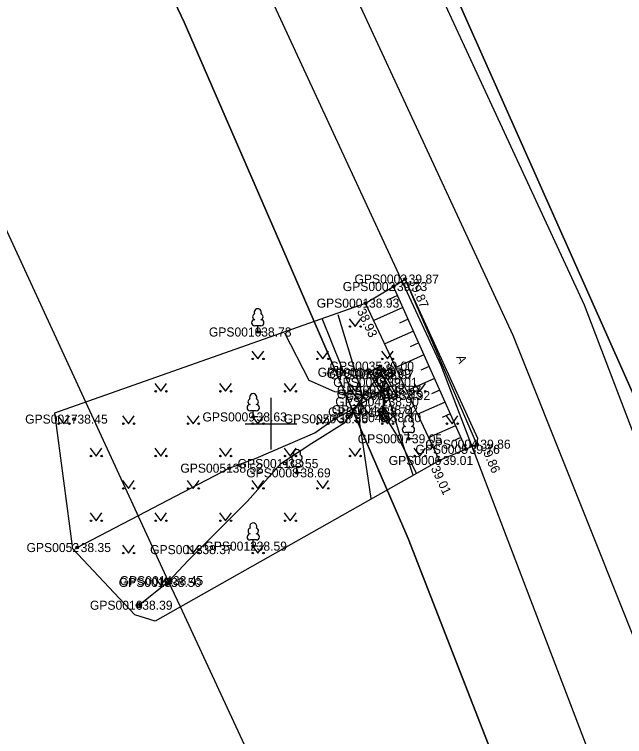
# Model space of a CAD drawing. Extents: x 626224 to 628280, y 6467750 to 6471135.
# Drawn here: x 627830.2 to 627877.3, y 6468325.8 to 6468381.6 of the extents above; entities that cross this region are included whole.
import ezdxf

# ---------------------------------------------------------------- set-up
doc = ezdxf.new("R2010")
doc.units = 0
for name, color, linetype in [('ELRAJATISMP', 7, 'Continuous'), ('HALJASTUS', 7, 'Continuous'), ('KORGUS-EH2000', 7, 'Continuous'), ('MOOTKORG-EH2000', 7, 'Continuous'), ('MOOTMPUNKT', 7, 'Continuous'), ('MOOTNR', 7, 'Continuous'), ('MOOTPIIR', 7, 'Continuous'), ('MPKAABEL', 7, 'Continuous'), ('MPOHULIIN', 7, 'Continuous'), ('PIIR', 7, 'Continuous'), ('POST', 7, 'Continuous'), ('PUU', 7, 'Continuous'), ('RAJATIS', 7, 'Continuous'), ('RELJEEF', 7, 'Continuous'), ('SIRAJATIS', 7, 'Continuous'), ('SITRASS', 7, 'Continuous'), ('TEE', 7, 'Continuous'), ('Tee Liiklusala', 7, 'Continuous'), ('Tee Põhimaantee Püsikate', 7, 'Continuous'), ('VORK', 7, 'Continuous')]:
    doc.layers.add(name, color=color, linetype=linetype)

msp = doc.modelspace()

# ---------------------------------------------------------------- linework, layer by layer
at = {"layer": 'ELRAJATISMP'}
for p, q in [((627858.5, 6468353.97), (627857.976, 6468353.684)), ((627858.63, 6468353.731), (627858.106, 6468353.446))]:
    msp.add_line(p, q, dxfattribs=at)
msp.add_lwpolyline([(627858.28, 6468354.375), (627858.851, 6468353.326), (627858.327, 6468353.04), (627857.755, 6468354.089)], close=True, dxfattribs=at)
at = {"layer": 'HALJASTUS'}
for p, q in [((627856.037, 6468358.107), (627856.5, 6468357.5)), ((627856.5, 6468357.5), (627856.946, 6468358.107)), ((627848.537, 6468355.607), (627849, 6468355)), ((627849, 6468355), (627849.446, 6468355.607)), ((627853.537, 6468355.607), (627854, 6468355)), ((627854, 6468355), (627854.446, 6468355.607)), ((627858.537, 6468355.607), (627859, 6468355)), ((627859, 6468355), (627859.446, 6468355.607)), ((627841.037, 6468353.107), (627841.5, 6468352.5)), ((627841.5, 6468352.5), (627841.946, 6468353.107)), ((627846.037, 6468353.107), (627846.5, 6468352.5)), ((627846.5, 6468352.5), (627846.946, 6468353.107)), ((627851.037, 6468353.107), (627851.5, 6468352.5)), ((627851.5, 6468352.5), (627851.946, 6468353.107)), ((627856.037, 6468353.107), (627856.5, 6468352.5)), ((627856.5, 6468352.5), (627856.946, 6468353.107)), ((627861.037, 6468353.107), (627861.5, 6468352.5)), ((627861.5, 6468352.5), (627861.946, 6468353.107)), ((627833.537, 6468350.607), (627834, 6468350)), ((627834, 6468350), (627834.446, 6468350.607)), ((627838.537, 6468350.607), (627839, 6468350)), ((627839, 6468350), (627839.446, 6468350.607)), ((627843.537, 6468350.607), (627844, 6468350)), ((627844, 6468350), (627844.446, 6468350.607)), ((627848.537, 6468350.607), (627849, 6468350)), ((627849, 6468350), (627849.446, 6468350.607)), ((627853.537, 6468350.607), (627854, 6468350)), ((627854, 6468350), (627854.446, 6468350.607)), ((627858.537, 6468350.607), (627859, 6468350)), ((627859, 6468350), (627859.446, 6468350.607)), ((627863.537, 6468350.607), (627864, 6468350)), ((627864, 6468350), (627864.446, 6468350.607)), ((627836.037, 6468348.107), (627836.5, 6468347.5)), ((627836.5, 6468347.5), (627836.946, 6468348.107)), ((627841.037, 6468348.107), (627841.5, 6468347.5)), ((627841.5, 6468347.5), (627841.946, 6468348.107)), ((627846.037, 6468348.107), (627846.5, 6468347.5)), ((627846.5, 6468347.5), (627846.946, 6468348.107)), ((627851.037, 6468348.107), (627851.5, 6468347.5)), ((627851.5, 6468347.5), (627851.946, 6468348.107)), ((627856.037, 6468348.107), (627856.5, 6468347.5)), ((627856.5, 6468347.5), (627856.946, 6468348.107)), ((627861.037, 6468348.107), (627861.5, 6468347.5)), ((627861.5, 6468347.5), (627861.946, 6468348.107)), ((627838.537, 6468345.607), (627839, 6468345)), ((627839, 6468345), (627839.446, 6468345.607)), ((627843.537, 6468345.607), (627844, 6468345)), ((627844, 6468345), (627844.446, 6468345.607)), ((627848.537, 6468345.607), (627849, 6468345)), ((627849, 6468345), (627849.446, 6468345.607)), ((627853.537, 6468345.607), (627854, 6468345)), ((627854, 6468345), (627854.446, 6468345.607)), ((627836.037, 6468343.107), (627836.5, 6468342.5)), ((627836.5, 6468342.5), (627836.946, 6468343.107)), ((627841.037, 6468343.107), (627841.5, 6468342.5)), ((627841.5, 6468342.5), (627841.946, 6468343.107)), ((627846.037, 6468343.107), (627846.5, 6468342.5)), ((627846.5, 6468342.5), (627846.946, 6468343.107)), ((627851.037, 6468343.107), (627851.5, 6468342.5)), ((627851.5, 6468342.5), (627851.946, 6468343.107)), ((627838.537, 6468340.607), (627839, 6468340)), ((627839, 6468340), (627839.446, 6468340.607)), ((627843.537, 6468340.607), (627844, 6468340)), ((627844, 6468340), (627844.446, 6468340.607)), ((627848.537, 6468340.607), (627849, 6468340)), ((627849, 6468340), (627849.446, 6468340.607)), ((627841.037, 6468338.107), (627841.5, 6468337.5)), ((627841.5, 6468337.5), (627841.946, 6468338.107))]:
    msp.add_line(p, q, dxfattribs=at)
for centre in [(627856.099, 6468357.5), (627856.928, 6468357.5), (627848.599, 6468355), (627849.428, 6468355), (627853.599, 6468355), (627854.428, 6468355), (627858.599, 6468355), (627859.428, 6468355), (627841.099, 6468352.5), (627841.928, 6468352.5), (627846.099, 6468352.5), (627846.928, 6468352.5), (627851.099, 6468352.5), (627851.928, 6468352.5), (627856.099, 6468352.5), (627856.928, 6468352.5), (627861.099, 6468352.5), (627861.928, 6468352.5), (627833.599, 6468350), (627834.428, 6468350), (627838.599, 6468350), (627839.428, 6468350), (627843.599, 6468350), (627844.428, 6468350), (627848.599, 6468350), (627849.428, 6468350), (627853.599, 6468350), (627854.428, 6468350), (627858.599, 6468350), (627859.428, 6468350), (627863.599, 6468350), (627864.428, 6468350), (627836.099, 6468347.5), (627836.928, 6468347.5), (627841.099, 6468347.5), (627841.928, 6468347.5), (627846.099, 6468347.5), (627846.928, 6468347.5), (627851.099, 6468347.5), (627851.928, 6468347.5), (627856.099, 6468347.5), (627856.928, 6468347.5), (627861.099, 6468347.5), (627861.928, 6468347.5), (627838.599, 6468345), (627839.428, 6468345), (627843.599, 6468345), (627844.428, 6468345), (627848.599, 6468345), (627849.428, 6468345), (627853.599, 6468345), (627854.428, 6468345), (627836.099, 6468342.5), (627836.928, 6468342.5), (627841.099, 6468342.5), (627841.928, 6468342.5), (627846.099, 6468342.5), (627846.928, 6468342.5), (627851.099, 6468342.5), (627851.928, 6468342.5), (627838.599, 6468340), (627839.428, 6468340), (627843.599, 6468340), (627844.428, 6468340), (627848.599, 6468340), (627849.428, 6468340), (627841.099, 6468337.5), (627841.928, 6468337.5)]:
    msp.add_circle(centre, 0.055, dxfattribs=at)
at = {"layer": 'KORGUS-EH2000'}
for centre in [(627860.38, 6468361.171), (627857.317, 6468359.31), (627848.989, 6468357.081), (627859.701, 6468352.173), (627834.793, 6468350.351), (627848.631, 6468350.521), (627865.917, 6468348.418), (627863.023, 6468347.157), (627852.014, 6468346.2), (627835.042, 6468340.431), (627848.637, 6468340.54), (627842.022, 6468337.736)]:
    msp.add_circle(centre, 0.1, dxfattribs=at)
at = {"layer": 'MOOTMPUNKT'}
for centre in [(627860.38, 6468361.171), (627859.472, 6468360.594), (627857.317, 6468359.31), (627848.989, 6468357.081), (627858.452, 6468354.446), (627857.604, 6468353.971), (627858.217, 6468353.866), (627858.436, 6468353.78), (627858.732, 6468353.192), (627859.026, 6468352.588), (627859.081, 6468352.281), (627859.701, 6468352.173), (627858.826, 6468351.698), (627858.41, 6468350.906), (627858.764, 6468351.073), (627834.793, 6468350.351), (627848.631, 6468350.521), (627854.91, 6468350.376), (627859.001, 6468350.463), (627860.628, 6468348.832), (627865.085, 6468348.018), (627865.917, 6468348.418), (627851.068, 6468346.918), (627863.023, 6468347.157), (627846.784, 6468346.562), (627852.014, 6468346.2), (627835.042, 6468340.431), (627844.448, 6468340.27), (627848.637, 6468340.54), (627842.166, 6468337.871), (627842.022, 6468337.736), (627839.799, 6468335.975)]:
    msp.add_circle(centre, 0.1, dxfattribs=at)
at = {"layer": 'MOOTPIIR'}
msp.add_lwpolyline([(627839.479, 6468335.233), (627834.702, 6468340.335), (627833.316, 6468350.832), (627857.317, 6468359.31), (627859.472, 6468360.594), (627860.38, 6468361.171), (627860.745, 6468360.332), (627865.969, 6468348.893), (627865.917, 6468348.418), (627865.085, 6468348.018), (627863.023, 6468347.157), (627841.067, 6468334.749)], close=True, dxfattribs=at)
at = {"layer": 'MPKAABEL'}
msp.add_lwpolyline([(627842.094, 6468337.804), (627843.616, 6468339.433), (627848.205, 6468344.015), (627850.765, 6468346.92), (627853.161, 6468348.505), (627855.705, 6468350.098), (627858.303, 6468353.708)], dxfattribs=at)
at = {"layer": 'MPOHULIIN'}
for points in [[(627835.693, 6468351.671), (627824.767, 6468375.343), (627808.334, 6468410.91), (627776.772, 6468462.547)], [(627843.004, 6468335.844), (627842.094, 6468337.804), (627835.693, 6468351.671)], [(627841.935, 6468203.359), (627866.718, 6468217.626), (627890.923, 6468231.653), (627883.458, 6468248.328), (627866.449, 6468285.338), (627843.004, 6468335.844)]]:
    msp.add_lwpolyline(points, dxfattribs=at)
at = {"layer": 'PIIR'}
for points in [[(627965.68, 6468502.25), (628025.29, 6468403.44), (627924.44, 6468351.42), (627930.15, 6468335.32), (627893.5, 6468317.49), (627836.88, 6468444.6), (627838.09, 6468445.14)], [(627802, 6468382.71), (627775.07, 6468451.79), (627801.28, 6468461.34), (627809.58, 6468448), (627816.81, 6468434.6), (627826.02, 6468416.53), (627834.21, 6468400.21), (627843.3, 6468381.02), (627850.92, 6468363.47), (627860.61, 6468341.12), (627869.05, 6468319.44), (627817.44, 6468300.95), (627762.12, 6468283.97), (627745.3, 6468323.41), (627778.35, 6468337.62), (627766.32, 6468369.86)]]:
    msp.add_lwpolyline(points, close=True, dxfattribs=at)
msp.add_lwpolyline([(627869.05, 6468319.44), (627860.61, 6468341.12), (627850.92, 6468363.47), (627843.3, 6468381.02), (627834.21, 6468400.21), (627826.02, 6468416.53), (627816.81, 6468434.6), (627809.58, 6468448), (627801.28, 6468461.34), (627796.62, 6468466.91), (627793.68, 6468471.35), (627793.54, 6468471.56), (627816.33, 6468482.77), (627818.92, 6468478.42), (627838.09, 6468445.14), (627836.88, 6468444.6), (627893.5, 6468317.49)], dxfattribs=at)
at = {"layer": 'POST'}
msp.add_lwpolyline([(627839.799, 6468335.975), (627842.094, 6468337.804)], dxfattribs=at)
for centre, radius in [((627842.094, 6468337.804), 0.25), ((627842.094, 6468337.804), 0.0234), ((627839.799, 6468335.975), 0.2)]:
    msp.add_circle(centre, radius, dxfattribs=at)
at = {"layer": 'PUU'}
for p, q in [((627849.229, 6468357.556), (627848.749, 6468357.556)), ((627848.989, 6468357.081), (627848.989, 6468357.556)), ((627849.369, 6468357.081), (627848.989, 6468357.081)), ((627848.872, 6468350.996), (627848.392, 6468350.996)), ((627848.631, 6468350.521), (627848.631, 6468350.996)), ((627849.012, 6468350.521), (627848.631, 6468350.521)), ((627860.868, 6468349.307), (627860.388, 6468349.307)), ((627860.628, 6468348.832), (627860.628, 6468349.307)), ((627861.008, 6468348.832), (627860.628, 6468348.832)), ((627852.254, 6468346.675), (627851.774, 6468346.675)), ((627852.014, 6468346.2), (627852.014, 6468346.675)), ((627852.394, 6468346.2), (627852.014, 6468346.2)), ((627848.877, 6468341.015), (627848.397, 6468341.015)), ((627848.637, 6468340.54), (627848.637, 6468341.015)), ((627849.017, 6468340.54), (627848.637, 6468340.54))]:
    msp.add_line(p, q, dxfattribs=at)
for centre, radius, start, end in [((627848.989, 6468358.601), 0.277, 332.5799, 207.4201), ((627848.751, 6468357.794), 0.238, 90.0016, 269.3953), ((627848.819, 6468358.254), 0.233, 109.0217, 253.1415), ((627849.159, 6468358.254), 0.233, 286.8508, 70.9859), ((627849.226, 6468357.794), 0.238, 270.6047, 89.9984), ((627848.461, 6468351.694), 0.233, 109.0217, 253.1415), ((627848.631, 6468352.041), 0.277, 332.5799, 207.4201), ((627848.802, 6468351.694), 0.233, 286.8508, 70.9859), ((627848.394, 6468351.234), 0.238, 90.0016, 269.3953), ((627848.869, 6468351.234), 0.238, 270.6047, 89.9984), ((627860.458, 6468350.004), 0.233, 109.0217, 253.1415), ((627860.628, 6468350.352), 0.277, 332.5799, 207.4201), ((627860.798, 6468350.004), 0.233, 286.8508, 70.9859), ((627860.39, 6468349.544), 0.238, 90.0016, 269.3953), ((627860.865, 6468349.544), 0.238, 270.6047, 89.9984), ((627852.014, 6468347.72), 0.277, 332.5799, 207.4201), ((627851.844, 6468347.373), 0.233, 109.0217, 253.1415), ((627852.184, 6468347.373), 0.233, 286.8508, 70.9859), ((627851.776, 6468346.913), 0.238, 90.0016, 269.3953), ((627852.251, 6468346.913), 0.238, 270.6047, 89.9984), ((627848.467, 6468341.713), 0.233, 109.0217, 253.1415), ((627848.637, 6468342.06), 0.277, 332.5799, 207.4201), ((627848.807, 6468341.713), 0.233, 286.8508, 70.9859), ((627848.399, 6468341.253), 0.238, 90.0016, 269.3953), ((627848.874, 6468341.253), 0.238, 270.6047, 89.9984)]:
    msp.add_arc(centre, radius, start, end, dxfattribs=at)
at = {"layer": 'RAJATIS'}
msp.add_lwpolyline([(627859.001, 6468350.463), (627858.774, 6468351.047), (627858.41, 6468350.906), (627858.637, 6468350.322)], close=True, dxfattribs=at)
at = {"layer": 'RELJEEF'}
for p, q in [((627865.085, 6468348.018), (627859.472, 6468360.594)), ((627859.787, 6468359.889), (627859.107, 6468359.586)), ((627863.023, 6468347.157), (627857.317, 6468359.31)), ((627860.194, 6468358.976), (627857.945, 6468357.972)), ((627860.602, 6468358.063), (627859.933, 6468357.764)), ((627861.01, 6468357.15), (627858.795, 6468356.162)), ((627861.417, 6468356.237), (627860.758, 6468355.943)), ((627861.825, 6468355.323), (627859.646, 6468354.351)), ((627862.232, 6468354.41), (627861.584, 6468354.121)), ((627862.64, 6468353.497), (627860.496, 6468352.54)), ((627863.047, 6468352.584), (627862.409, 6468352.299)), ((627863.455, 6468351.671), (627861.346, 6468350.729)), ((627863.862, 6468350.757), (627863.235, 6468350.477)), ((627864.27, 6468349.844), (627862.196, 6468348.919)), ((627864.677, 6468348.931), (627864.06, 6468348.656))]:
    msp.add_line(p, q, dxfattribs=at)
at = {"layer": 'SIRAJATIS'}
for points in [[(627858.643, 6468353.712), (627859.121, 6468352.834), (627858.594, 6468352.547), (627858.116, 6468353.425)], [(627858.963, 6468353.124), (627859.442, 6468352.246), (627858.915, 6468351.958), (627858.436, 6468352.837)], [(627858.809, 6468351.273), (627859.188, 6468350.348), (627858.633, 6468350.12), (627858.254, 6468351.046)]]:
    msp.add_lwpolyline(points, close=True, dxfattribs=at)
for centre, radius in [((627858.523, 6468353.305), 0.0304), ((627858.523, 6468353.305), 0.029), ((627858.523, 6468353.305), 0.0277), ((627858.523, 6468353.305), 0.0263), ((627858.523, 6468353.305), 0.0249), ((627858.523, 6468353.305), 0.0236), ((627858.523, 6468353.305), 0.0222), ((627858.523, 6468353.305), 0.0209), ((627858.523, 6468353.305), 0.0195), ((627858.523, 6468353.305), 0.0181), ((627858.523, 6468353.305), 0.0168), ((627858.523, 6468353.305), 0.0154), ((627858.523, 6468353.305), 0.014), ((627858.523, 6468353.305), 0.0127), ((627858.523, 6468353.305), 0.0113), ((627858.523, 6468353.305), 0.00996), ((627858.523, 6468353.305), 0.0086), ((627858.523, 6468353.305), 0.00724), ((627858.523, 6468353.305), 0.00587), ((627858.523, 6468353.305), 0.00451), ((627858.523, 6468353.305), 0.00315), ((627858.523, 6468353.305), 0.00179), ((627858.523, 6468353.305), 0.000426), ((627858.714, 6468352.954), 0.0304), ((627858.714, 6468352.954), 0.029), ((627858.714, 6468352.954), 0.0277), ((627858.714, 6468352.954), 0.0263), ((627858.714, 6468352.954), 0.0249), ((627858.714, 6468352.954), 0.0236), ((627858.714, 6468352.954), 0.0222), ((627858.714, 6468352.954), 0.0209), ((627858.714, 6468352.954), 0.0195), ((627858.714, 6468352.954), 0.0181), ((627858.714, 6468352.954), 0.0168), ((627858.714, 6468352.954), 0.0154), ((627858.714, 6468352.954), 0.014), ((627858.714, 6468352.954), 0.0127), ((627858.714, 6468352.954), 0.0113), ((627858.714, 6468352.954), 0.00996), ((627858.714, 6468352.954), 0.0086), ((627858.714, 6468352.954), 0.00724), ((627858.714, 6468352.954), 0.00587), ((627858.714, 6468352.954), 0.00451), ((627858.714, 6468352.954), 0.00315), ((627858.714, 6468352.954), 0.00179), ((627858.714, 6468352.954), 0.000426), ((627858.843, 6468352.717), 0.0304), ((627858.843, 6468352.717), 0.029), ((627858.843, 6468352.717), 0.0277), ((627858.843, 6468352.717), 0.0263), ((627858.843, 6468352.717), 0.0249), ((627858.843, 6468352.717), 0.0236), ((627858.843, 6468352.717), 0.0222), ((627858.843, 6468352.717), 0.0209), ((627858.843, 6468352.717), 0.0195), ((627858.843, 6468352.717), 0.0181), ((627858.843, 6468352.717), 0.0168), ((627858.843, 6468352.717), 0.0154), ((627858.843, 6468352.717), 0.014), ((627858.843, 6468352.717), 0.0127), ((627858.843, 6468352.717), 0.0113), ((627858.843, 6468352.717), 0.00996), ((627858.843, 6468352.717), 0.0086), ((627858.843, 6468352.717), 0.00724), ((627858.843, 6468352.717), 0.00587), ((627858.843, 6468352.717), 0.00451), ((627858.843, 6468352.717), 0.00315), ((627858.843, 6468352.717), 0.00179), ((627858.843, 6468352.717), 0.000426), ((627859.035, 6468352.365), 0.0304), ((627859.035, 6468352.365), 0.029), ((627859.035, 6468352.365), 0.0277), ((627859.035, 6468352.365), 0.0263), ((627859.035, 6468352.365), 0.0249), ((627859.035, 6468352.365), 0.0236), ((627859.035, 6468352.365), 0.0222), ((627859.035, 6468352.365), 0.0209), ((627859.035, 6468352.365), 0.0195), ((627859.035, 6468352.365), 0.0181), ((627859.035, 6468352.365), 0.0168), ((627859.035, 6468352.365), 0.0154), ((627859.035, 6468352.365), 0.014), ((627859.035, 6468352.365), 0.0127), ((627859.035, 6468352.365), 0.0113), ((627859.035, 6468352.365), 0.00996), ((627859.035, 6468352.365), 0.0086), ((627859.035, 6468352.365), 0.00724), ((627859.035, 6468352.365), 0.00587), ((627859.035, 6468352.365), 0.00451), ((627859.035, 6468352.365), 0.00315), ((627859.035, 6468352.365), 0.00179), ((627859.035, 6468352.365), 0.000426), ((627858.645, 6468350.882), 0.0304), ((627858.645, 6468350.882), 0.029), ((627858.645, 6468350.882), 0.0277), ((627858.645, 6468350.882), 0.0263), ((627858.645, 6468350.882), 0.0249), ((627858.645, 6468350.882), 0.0236), ((627858.645, 6468350.882), 0.0222), ((627858.645, 6468350.882), 0.0209), ((627858.645, 6468350.882), 0.0195), ((627858.645, 6468350.882), 0.0181), ((627858.645, 6468350.882), 0.0168), ((627858.645, 6468350.882), 0.0154), ((627858.645, 6468350.882), 0.014), ((627858.645, 6468350.882), 0.0127), ((627858.645, 6468350.882), 0.0113), ((627858.645, 6468350.882), 0.00996), ((627858.645, 6468350.882), 0.0086), ((627858.645, 6468350.882), 0.00724), ((627858.645, 6468350.882), 0.00587), ((627858.645, 6468350.882), 0.00451), ((627858.645, 6468350.882), 0.00315), ((627858.645, 6468350.882), 0.00179), ((627858.645, 6468350.882), 0.000426), ((627858.797, 6468350.512), 0.0304), ((627858.797, 6468350.512), 0.029), ((627858.797, 6468350.512), 0.0277), ((627858.797, 6468350.512), 0.0263), ((627858.797, 6468350.512), 0.0249), ((627858.797, 6468350.512), 0.0236), ((627858.797, 6468350.512), 0.0222), ((627858.797, 6468350.512), 0.0209), ((627858.797, 6468350.512), 0.0195), ((627858.797, 6468350.512), 0.0181), ((627858.797, 6468350.512), 0.0168), ((627858.797, 6468350.512), 0.0154), ((627858.797, 6468350.512), 0.014), ((627858.797, 6468350.512), 0.0127), ((627858.797, 6468350.512), 0.0113), ((627858.797, 6468350.512), 0.00996), ((627858.797, 6468350.512), 0.0086), ((627858.797, 6468350.512), 0.00724), ((627858.797, 6468350.512), 0.00587), ((627858.797, 6468350.512), 0.00451), ((627858.797, 6468350.512), 0.00315), ((627858.797, 6468350.512), 0.00179), ((627858.797, 6468350.512), 0.000426)]:
    msp.add_circle(centre, radius, dxfattribs=at)
at = {"layer": 'SITRASS'}
for points in [[(627858.721, 6468350.697), (627857.741, 6468350.531), (627856.189, 6468352.574), (627853.958, 6468358.124)], [(627857.745, 6468344.219), (627857.143, 6468348.215), (627856.848, 6468350.174), (627857.076, 6468352.201), (627855.207, 6468358.41)], [(627858.939, 6468352.541), (627857.076, 6468352.201), (627854.93, 6468352.451), (627852.951, 6468353.342), (627851.083, 6468356.982)], [(627858.627, 6468353.097), (627858.707, 6468350.76)], [(627835.042, 6468340.431), (627846.784, 6468346.562), (627848.859, 6468347.329), (627853.384, 6468349.294), (627854.91, 6468350.376), (627855.525, 6468350.694), (627857.957, 6468352.139), (627858.939, 6468352.541)], [(627858.939, 6468352.541), (627859.905, 6468349.271), (627860.965, 6468346.048)], [(627858.721, 6468350.697), (627859.876, 6468348.833), (627861.241, 6468346.151)]]:
    msp.add_lwpolyline(points, dxfattribs=at)
at = {"layer": 'TEE'}
msp.add_line((627865.917, 6468348.418), (627860.38, 6468361.171), dxfattribs=at)
msp.add_lwpolyline([(627858.826, 6468351.698), (627857.604, 6468353.971), (627858.452, 6468354.446), (627859.701, 6468352.173), (627858.826, 6468351.698)], dxfattribs=at)
at = {"layer": 'Tee Liiklusala'}
for points in [[(628004.712, 6467966.979), (627997.81, 6467987.98), (627990.136, 6468009.252), (627982.428, 6468031.57), (627970.386, 6468066.341), (627943.56, 6468142.05), (627938.773, 6468155.662), (627916.353, 6468218.793), (627896.06, 6468271.56), (627889.692, 6468286.926), (627880.369, 6468309.48), (627875.602, 6468321.934), (627863.15, 6468354.49), (627844.06, 6468395.68), (627818.98, 6468444.86), (627806.067, 6468466.343), (627794.52, 6468485.83), (627778.37, 6468512.41), (627770.48, 6468525.39), (627740.557, 6468568.764)], [(627760.92, 6468560.36), (627780.56, 6468531.91), (627795.194, 6468507.826), (627804.8, 6468492.03), (627819.213, 6468468.282), (627829.48, 6468450.66), (627842.629, 6468424.884), (627852.37, 6468405.79), (627854.86, 6468400.94), (627874.21, 6468359.17), (627891.81, 6468313.11), (627897.891, 6468298.46), (627907.18, 6468276.08), (627914.223, 6468258.331), (627924.31, 6468232.91), (627926.05, 6468227.94), (627930.17, 6468216.22), (627939.76, 6468188.97), (627954.88, 6468146.07), (627973.905, 6468092.359), (627984.638, 6468061.117)]]:
    msp.add_lwpolyline(points, dxfattribs=at)
at = {"layer": 'Tee Põhimaantee Püsikate'}
msp.add_lwpolyline([(627812.119, 6468468.847), (627818.257, 6468457.757), (627833.152, 6468430.273), (627849.46, 6468398.31), (627868.68, 6468356.83), (627882.943, 6468321.192), (627886.597, 6468311.791)], dxfattribs=at)
at = {"layer": 'VORK'}
for p, q in [((627850, 6468352), (627850, 6468348)), ((627848, 6468350), (627852, 6468350))]:
    msp.add_line(p, q, dxfattribs=at)

# ---------------------------------------------------------------- texts
at = {"layer": 'KORGUS-EH2000'}
for s, rotation, p in [(' 39.87', 293.47, (627860.54, 6468361.24)), (' 38.93', 295.1495, (627856.525, 6468358.939)), (' 38.92', 303.163, (627858.395, 6468354.557)), (' 39.86', 293.47, (627866.077, 6468348.487)), (' 39.01', 295.1495, (627862.231, 6468346.786))]:
    msp.add_text(s, height=0.7, rotation=rotation, dxfattribs=at).set_placement(p)
for s, p in [(' 38.78', (627848.989, 6468356.731)), (' 38.63', (627848.631, 6468350.171)), (' 38.45', (627834.793, 6468350.001)), (' 38.69', (627852.014, 6468345.85)), (' 38.35', (627835.042, 6468340.081)), (' 38.59', (627848.637, 6468340.19)), (' 38.50', (627842.022, 6468337.386))]:
    msp.add_text(s, height=0.7, dxfattribs=at).set_placement(p)
at = {"layer": 'MOOTKORG-EH2000'}
for s, p in [(' 39.87', (627860.38, 6468360.821)), (' 39.73', (627859.472, 6468360.244)), (' 38.93', (627857.317, 6468358.96)), (' 38.78', (627848.989, 6468356.731)), (' 39.00', (627858.452, 6468354.096)), (' 38.97', (627857.604, 6468353.621)), (' 38.99', (627858.217, 6468353.516)), (' 38.97', (627858.436, 6468353.43)), (' 39.01', (627858.732, 6468352.842)), (' 38.97', (627859.026, 6468352.238)), (' 38.95', (627859.081, 6468351.931)), (' 38.92', (627859.701, 6468351.823)), (' 38.90', (627858.826, 6468351.348)), (' 38.82', (627858.764, 6468350.723)), (' 38.63', (627848.631, 6468350.171)), (' 38.74', (627858.41, 6468350.556)), (' 38.80', (627859.001, 6468350.113)), (' 38.45', (627834.793, 6468350.001)), (' 38.85', (627854.91, 6468350.026)), (' 39.05', (627860.628, 6468348.482)), (' 39.86', (627865.917, 6468348.067)), (' 39.76', (627865.085, 6468347.668)), (' 39.01', (627863.023, 6468346.807)), (' 38.52', (627846.784, 6468346.212)), (' 38.55', (627851.068, 6468346.568)), (' 38.69', (627852.014, 6468345.85)), (' 38.35', (627835.042, 6468340.081)), (' 38.59', (627848.637, 6468340.19)), (' 38.37', (627844.448, 6468339.92)), (' 38.50', (627842.022, 6468337.386)), (' 38.45', (627842.166, 6468337.521)), (' 38.39', (627839.799, 6468335.625))]:
    msp.add_text(s, height=0.7, dxfattribs=at).set_placement(p)
at = {"layer": 'MOOTNR'}
for s, p in [('GPS0003 ', (627856.46, 6468360.821)), ('GPS0002 ', (627855.552, 6468360.244)), ('GPS0001 ', (627853.537, 6468358.96)), ('GPS0010 ', (627845.209, 6468356.731)), ('GPS0035 ', (627854.532, 6468354.096)), ('GPS0034 ', (627853.614, 6468353.621)), ('GPS0036 ', (627854.297, 6468353.516)), ('GPS0037 ', (627854.516, 6468353.43)), ('GPS0038 ', (627854.812, 6468352.842)), ('GPS0042 ', (627855.091, 6468351.931)), ('GPS0039 ', (627855.106, 6468352.238)), ('GPS0040 ', (627855.712, 6468351.823)), ('GPS0041 ', (627854.976, 6468351.348)), ('GPS0044 ', (627854.705, 6468350.723)), ('GPS0009 ', (627844.712, 6468350.171)), ('GPS0043 ', (627854.42, 6468350.556)), ('GPS0045 ', (627855.011, 6468350.113)), ('GPS0017 ', (627831.013, 6468350.001)), ('GPS0050 ', (627850.99, 6468350.026)), ('GPS0007 ', (627856.708, 6468348.482)), ('GPS0004 ', (627861.927, 6468348.067)), ('GPS0005 ', (627861.165, 6468347.668)), ('GPS0006 ', (627859.103, 6468346.807)), ('GPS0051 ', (627843.004, 6468346.212)), ('GPS0011 ', (627847.428, 6468346.568)), ('GPS0008 ', (627848.094, 6468345.85)), ('GPS0052 ', (627831.122, 6468340.081)), ('GPS0012 ', (627844.857, 6468340.19)), ('GPS0013 ', (627840.668, 6468339.92)), ('GPS0015 ', (627838.243, 6468337.386)), ('GPS0014 ', (627838.316, 6468337.521)), ('GPS0016 ', (627836.019, 6468335.625))]:
    msp.add_text(s, height=0.7, dxfattribs=at).set_placement(p)
at = {"layer": 'TEE'}
msp.add_text('A', height=0.7, rotation=292.0081, dxfattribs=at).set_placement((627864.301, 6468355.146))

doc.saveas('drawing.dxf')
